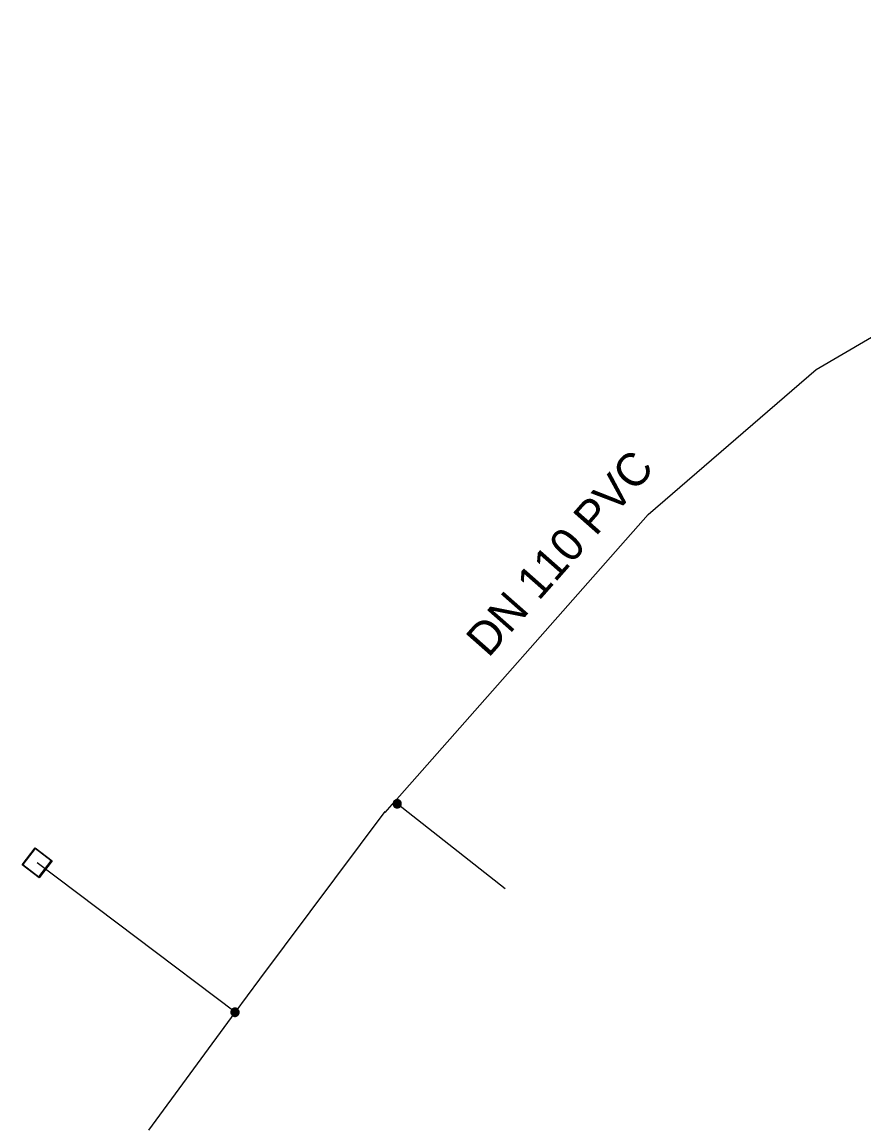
# Model space of a CAD drawing. Extents: x -832382 to -831581, y -1074670 to -1074251.
# Drawn here: x -831785.8 to -831734.8, y -1074502.9 to -1074436.2 of the extents above; entities that cross this region are included whole.
import ezdxf

# ---------------------------------------------------------------- set-up
doc = ezdxf.new("R2010")
doc.units = 0
for name, color, linetype in [('Přípojka vodovodu', 7, 'Continuous'), ('Přípojkový uzávěr', 7, 'Continuous'), ('Roz-řad', 7, 'Continuous'), ('Roz-řad-popis základní', 7, 'Continuous'), ('Šachta vodovodní', 7, 'Continuous')]:
    doc.layers.add(name, color=color, linetype=linetype)

msp = doc.modelspace()

# ---------------------------------------------------------------- linework, layer by layer
at = {"layer": 'Přípojka vodovodu'}
for points in [[(-831756.508, -1074488.677), (-831763.04, -1074483.52), (-831763.194, -1074483.398)], [(-831772.842, -1074496.164), (-831772.86, -1074496.15), (-831784.847, -1074487.094)]]:
    msp.add_lwpolyline(points, dxfattribs=at)
at = {"layer": 'Přípojkový uzávěr'}
for points in [[(-831763.04, -1074483.27), (-831762.977, -1074483.27), (-831762.917, -1074483.302), (-831762.858, -1074483.334), (-831762.824, -1074483.395), (-831762.79, -1074483.455), (-831762.79, -1074483.52), (-831762.79, -1074483.585), (-831762.823, -1074483.645), (-831762.856, -1074483.704), (-831762.915, -1074483.737), (-831762.975, -1074483.77), (-831763.04, -1074483.77), (-831763.105, -1074483.77), (-831763.165, -1074483.737), (-831763.224, -1074483.704), (-831763.257, -1074483.645), (-831763.29, -1074483.585), (-831763.29, -1074483.52), (-831763.29, -1074483.455), (-831763.256, -1074483.395), (-831763.223, -1074483.334), (-831763.163, -1074483.302), (-831763.103, -1074483.27), (-831763.04, -1074483.27)], [(-831763.04, -1074483.293), (-831763.097, -1074483.293), (-831763.152, -1074483.323), (-831763.206, -1074483.352), (-831763.236, -1074483.406), (-831763.267, -1074483.461), (-831763.267, -1074483.52), (-831763.267, -1074483.579), (-831763.237, -1074483.633), (-831763.207, -1074483.687), (-831763.153, -1074483.717), (-831763.099, -1074483.747), (-831763.04, -1074483.747), (-831762.981, -1074483.747), (-831762.927, -1074483.717), (-831762.873, -1074483.687), (-831762.843, -1074483.633), (-831762.813, -1074483.579), (-831762.813, -1074483.52), (-831762.813, -1074483.461), (-831762.844, -1074483.406), (-831762.875, -1074483.352), (-831762.929, -1074483.323), (-831762.983, -1074483.293), (-831763.04, -1074483.293)], [(-831763.04, -1074483.311), (-831762.987, -1074483.311), (-831762.937, -1074483.338), (-831762.887, -1074483.364), (-831762.859, -1074483.415), (-831762.831, -1074483.465), (-831762.831, -1074483.52), (-831762.831, -1074483.575), (-831762.858, -1074483.624), (-831762.885, -1074483.674), (-831762.936, -1074483.702), (-831762.986, -1074483.729), (-831763.04, -1074483.729), (-831763.094, -1074483.729), (-831763.144, -1074483.702), (-831763.195, -1074483.674), (-831763.222, -1074483.624), (-831763.249, -1074483.575), (-831763.249, -1074483.52), (-831763.249, -1074483.465), (-831763.221, -1074483.415), (-831763.193, -1074483.364), (-831763.143, -1074483.338), (-831763.093, -1074483.311), (-831763.04, -1074483.311)], [(-831763.04, -1074483.333), (-831763.119, -1074483.333), (-831763.173, -1074483.387), (-831763.228, -1074483.442), (-831763.228, -1074483.52), (-831763.228, -1074483.598), (-831763.173, -1074483.653), (-831763.118, -1074483.708), (-831763.04, -1074483.708), (-831762.962, -1074483.708), (-831762.907, -1074483.653), (-831762.853, -1074483.598), (-831762.853, -1074483.52), (-831762.853, -1074483.442), (-831762.907, -1074483.387), (-831762.962, -1074483.333), (-831763.04, -1074483.333)], [(-831763.04, -1074483.355), (-831762.972, -1074483.355), (-831762.924, -1074483.403), (-831762.876, -1074483.451), (-831762.876, -1074483.52), (-831762.876, -1074483.588), (-831762.924, -1074483.636), (-831762.972, -1074483.684), (-831763.04, -1074483.684), (-831763.109, -1074483.684), (-831763.157, -1074483.636), (-831763.205, -1074483.588), (-831763.205, -1074483.52), (-831763.205, -1074483.451), (-831763.157, -1074483.403), (-831763.109, -1074483.355), (-831763.04, -1074483.355)], [(-831763.04, -1074483.375), (-831763.101, -1074483.375), (-831763.143, -1074483.417), (-831763.185, -1074483.46), (-831763.185, -1074483.52), (-831763.185, -1074483.579), (-831763.143, -1074483.622), (-831763.101, -1074483.664), (-831763.04, -1074483.664), (-831762.981, -1074483.664), (-831762.938, -1074483.622), (-831762.896, -1074483.579), (-831762.896, -1074483.52), (-831762.896, -1074483.46), (-831762.938, -1074483.417), (-831762.98, -1074483.375), (-831763.04, -1074483.375)], [(-831763.04, -1074483.395), (-831762.988, -1074483.395), (-831762.951, -1074483.432), (-831762.915, -1074483.468), (-831762.915, -1074483.52), (-831762.915, -1074483.572), (-831762.952, -1074483.609), (-831762.988, -1074483.645), (-831763.04, -1074483.645), (-831763.092, -1074483.645), (-831763.128, -1074483.609), (-831763.165, -1074483.572), (-831763.165, -1074483.52), (-831763.165, -1074483.468), (-831763.129, -1074483.432), (-831763.092, -1074483.395), (-831763.04, -1074483.395)], [(-831763.04, -1074483.418), (-831763.082, -1074483.418), (-831763.112, -1074483.448), (-831763.142, -1074483.478), (-831763.142, -1074483.52), (-831763.142, -1074483.562), (-831763.112, -1074483.592), (-831763.082, -1074483.621), (-831763.04, -1074483.621), (-831762.998, -1074483.621), (-831762.968, -1074483.592), (-831762.939, -1074483.562), (-831762.939, -1074483.52), (-831762.939, -1074483.478), (-831762.968, -1074483.448), (-831762.998, -1074483.418), (-831763.04, -1074483.418)], [(-831763.04, -1074483.436), (-831763.005, -1074483.436), (-831762.981, -1074483.46), (-831762.956, -1074483.485), (-831762.956, -1074483.52), (-831762.956, -1074483.555), (-831762.981, -1074483.579), (-831763.005, -1074483.604), (-831763.04, -1074483.604), (-831763.075, -1074483.604), (-831763.1, -1074483.579), (-831763.124, -1074483.555), (-831763.124, -1074483.52), (-831763.124, -1074483.485), (-831763.1, -1074483.46), (-831763.075, -1074483.436), (-831763.04, -1074483.436)], [(-831763.04, -1074483.458), (-831763.066, -1074483.458), (-831763.084, -1074483.476), (-831763.103, -1074483.494), (-831763.103, -1074483.52), (-831763.103, -1074483.546), (-831763.084, -1074483.564), (-831763.066, -1074483.583), (-831763.04, -1074483.583), (-831763.014, -1074483.583), (-831762.996, -1074483.564), (-831762.978, -1074483.546), (-831762.978, -1074483.52), (-831762.978, -1074483.494), (-831762.996, -1074483.476), (-831763.014, -1074483.458), (-831763.04, -1074483.458)], [(-831763.04, -1074483.481), (-831763.024, -1074483.481), (-831763.012, -1074483.492), (-831763.001, -1074483.503), (-831763.001, -1074483.52), (-831763.001, -1074483.536), (-831763.012, -1074483.548), (-831763.024, -1074483.559), (-831763.04, -1074483.559), (-831763.056, -1074483.559), (-831763.068, -1074483.548), (-831763.079, -1074483.536), (-831763.079, -1074483.52), (-831763.079, -1074483.503), (-831763.068, -1074483.492), (-831763.056, -1074483.481), (-831763.04, -1074483.481)], [(-831763.04, -1074483.497), (-831763.05, -1074483.497), (-831763.057, -1074483.503), (-831763.064, -1074483.51), (-831763.064, -1074483.52), (-831763.064, -1074483.53), (-831763.057, -1074483.537), (-831763.05, -1074483.543), (-831763.04, -1074483.543), (-831763.03, -1074483.543), (-831763.024, -1074483.537), (-831763.017, -1074483.53), (-831763.017, -1074483.52), (-831763.017, -1074483.51), (-831763.024, -1074483.503), (-831763.03, -1074483.497), (-831763.04, -1074483.497)], [(-831772.86, -1074495.9), (-831772.797, -1074495.9), (-831772.737, -1074495.932), (-831772.678, -1074495.964), (-831772.644, -1074496.025), (-831772.61, -1074496.085), (-831772.61, -1074496.15), (-831772.61, -1074496.215), (-831772.643, -1074496.275), (-831772.676, -1074496.334), (-831772.735, -1074496.367), (-831772.795, -1074496.4), (-831772.86, -1074496.4), (-831772.925, -1074496.4), (-831772.985, -1074496.367), (-831773.044, -1074496.334), (-831773.077, -1074496.275), (-831773.11, -1074496.215), (-831773.11, -1074496.15), (-831773.11, -1074496.085), (-831773.076, -1074496.025), (-831773.043, -1074495.964), (-831772.983, -1074495.932), (-831772.923, -1074495.9), (-831772.86, -1074495.9)], [(-831772.86, -1074495.923), (-831772.917, -1074495.923), (-831772.972, -1074495.953), (-831773.026, -1074495.982), (-831773.056, -1074496.036), (-831773.087, -1074496.091), (-831773.087, -1074496.15), (-831773.087, -1074496.209), (-831773.057, -1074496.263), (-831773.027, -1074496.317), (-831772.973, -1074496.347), (-831772.919, -1074496.377), (-831772.86, -1074496.377), (-831772.801, -1074496.377), (-831772.747, -1074496.347), (-831772.693, -1074496.317), (-831772.663, -1074496.263), (-831772.633, -1074496.209), (-831772.633, -1074496.15), (-831772.633, -1074496.091), (-831772.664, -1074496.036), (-831772.695, -1074495.982), (-831772.749, -1074495.953), (-831772.803, -1074495.923), (-831772.86, -1074495.923)], [(-831772.86, -1074495.941), (-831772.807, -1074495.941), (-831772.757, -1074495.968), (-831772.707, -1074495.994), (-831772.679, -1074496.045), (-831772.651, -1074496.095), (-831772.651, -1074496.15), (-831772.651, -1074496.205), (-831772.678, -1074496.254), (-831772.705, -1074496.304), (-831772.756, -1074496.332), (-831772.806, -1074496.359), (-831772.86, -1074496.359), (-831772.914, -1074496.359), (-831772.964, -1074496.332), (-831773.015, -1074496.304), (-831773.042, -1074496.254), (-831773.069, -1074496.205), (-831773.069, -1074496.15), (-831773.069, -1074496.095), (-831773.041, -1074496.045), (-831773.013, -1074495.994), (-831772.963, -1074495.968), (-831772.913, -1074495.941), (-831772.86, -1074495.941)], [(-831772.86, -1074495.962), (-831772.939, -1074495.962), (-831772.993, -1074496.017), (-831773.047, -1074496.072), (-831773.047, -1074496.15), (-831773.047, -1074496.228), (-831772.993, -1074496.283), (-831772.938, -1074496.337), (-831772.86, -1074496.337), (-831772.782, -1074496.337), (-831772.727, -1074496.283), (-831772.672, -1074496.228), (-831772.672, -1074496.15), (-831772.672, -1074496.072), (-831772.727, -1074496.017), (-831772.782, -1074495.962), (-831772.86, -1074495.962)], [(-831772.86, -1074495.985), (-831772.792, -1074495.985), (-831772.744, -1074496.033), (-831772.696, -1074496.081), (-831772.696, -1074496.15), (-831772.696, -1074496.218), (-831772.744, -1074496.266), (-831772.792, -1074496.314), (-831772.86, -1074496.314), (-831772.929, -1074496.314), (-831772.977, -1074496.266), (-831773.025, -1074496.218), (-831773.025, -1074496.15), (-831773.025, -1074496.081), (-831772.977, -1074496.033), (-831772.929, -1074495.985), (-831772.86, -1074495.985)], [(-831772.86, -1074496.005), (-831772.921, -1074496.005), (-831772.963, -1074496.047), (-831773.005, -1074496.09), (-831773.005, -1074496.15), (-831773.005, -1074496.209), (-831772.963, -1074496.252), (-831772.921, -1074496.294), (-831772.86, -1074496.294), (-831772.801, -1074496.294), (-831772.758, -1074496.252), (-831772.716, -1074496.209), (-831772.716, -1074496.15), (-831772.716, -1074496.09), (-831772.758, -1074496.047), (-831772.8, -1074496.005), (-831772.86, -1074496.005)], [(-831772.86, -1074496.025), (-831772.808, -1074496.025), (-831772.771, -1074496.062), (-831772.735, -1074496.098), (-831772.735, -1074496.15), (-831772.735, -1074496.202), (-831772.772, -1074496.239), (-831772.808, -1074496.275), (-831772.86, -1074496.275), (-831772.912, -1074496.275), (-831772.948, -1074496.239), (-831772.985, -1074496.202), (-831772.985, -1074496.15), (-831772.985, -1074496.098), (-831772.949, -1074496.062), (-831772.912, -1074496.025), (-831772.86, -1074496.025)], [(-831772.86, -1074496.048), (-831772.902, -1074496.048), (-831772.932, -1074496.078), (-831772.962, -1074496.108), (-831772.962, -1074496.15), (-831772.962, -1074496.192), (-831772.932, -1074496.222), (-831772.902, -1074496.251), (-831772.86, -1074496.251), (-831772.818, -1074496.251), (-831772.788, -1074496.222), (-831772.759, -1074496.192), (-831772.759, -1074496.15), (-831772.759, -1074496.108), (-831772.788, -1074496.078), (-831772.818, -1074496.048), (-831772.86, -1074496.048)], [(-831772.86, -1074496.066), (-831772.825, -1074496.066), (-831772.801, -1074496.09), (-831772.776, -1074496.115), (-831772.776, -1074496.15), (-831772.776, -1074496.185), (-831772.801, -1074496.209), (-831772.825, -1074496.234), (-831772.86, -1074496.234), (-831772.895, -1074496.234), (-831772.92, -1074496.209), (-831772.944, -1074496.185), (-831772.944, -1074496.15), (-831772.944, -1074496.115), (-831772.92, -1074496.09), (-831772.895, -1074496.066), (-831772.86, -1074496.066)], [(-831772.86, -1074496.087), (-831772.886, -1074496.087), (-831772.904, -1074496.106), (-831772.922, -1074496.124), (-831772.922, -1074496.15), (-831772.922, -1074496.176), (-831772.904, -1074496.194), (-831772.886, -1074496.212), (-831772.86, -1074496.212), (-831772.834, -1074496.212), (-831772.816, -1074496.194), (-831772.797, -1074496.176), (-831772.797, -1074496.15), (-831772.797, -1074496.124), (-831772.816, -1074496.106), (-831772.834, -1074496.087), (-831772.86, -1074496.087)], [(-831772.86, -1074496.111), (-831772.844, -1074496.111), (-831772.832, -1074496.122), (-831772.821, -1074496.133), (-831772.821, -1074496.15), (-831772.821, -1074496.166), (-831772.832, -1074496.178), (-831772.844, -1074496.189), (-831772.86, -1074496.189), (-831772.876, -1074496.189), (-831772.888, -1074496.178), (-831772.899, -1074496.166), (-831772.899, -1074496.15), (-831772.899, -1074496.133), (-831772.888, -1074496.122), (-831772.876, -1074496.111), (-831772.86, -1074496.111)], [(-831772.86, -1074496.127), (-831772.87, -1074496.127), (-831772.877, -1074496.133), (-831772.884, -1074496.14), (-831772.884, -1074496.15), (-831772.884, -1074496.16), (-831772.877, -1074496.167), (-831772.87, -1074496.173), (-831772.86, -1074496.173), (-831772.85, -1074496.173), (-831772.844, -1074496.167), (-831772.837, -1074496.16), (-831772.837, -1074496.15), (-831772.837, -1074496.14), (-831772.844, -1074496.133), (-831772.85, -1074496.127), (-831772.86, -1074496.127)]]:
    msp.add_open_spline(points, degree=3, dxfattribs=at)
at = {"layer": 'Roz-řad'}
msp.add_lwpolyline([(-831778.085, -1074503.291), (-831772.842, -1074496.164), (-831771.36, -1074494.15), (-831763.76, -1074483.99), (-831763.769, -1074484.049), (-831763.194, -1074483.398), (-831747.84, -1074465.99), (-831737.66, -1074457.22), (-831726.547, -1074450.718), (-831715.985, -1074444.538), (-831707.51, -1074439.58), (-831699.57, -1074436.17)], dxfattribs=at)
at = {"layer": 'Šachta vodovodní'}
for points in [[(-831783.936, -1074486.971), (-831784.724, -1074488.005), (-831785.758, -1074487.217), (-831784.97, -1074486.183), (-831783.936, -1074486.971)], [(-831784.962, -1074486.24), (-831785.701, -1074487.209), (-831784.732, -1074487.948), (-831783.993, -1074486.979), (-831784.962, -1074486.24)]]:
    msp.add_lwpolyline(points, dxfattribs=at)

# ---------------------------------------------------------------- texts
at = {"layer": 'Roz-řad-popis základní'}
msp.add_text('DN 110 PVC', height=2, rotation=48.58602, dxfattribs=at).set_placement((-831757.516, -1074474.727))

doc.saveas('drawing.dxf')
